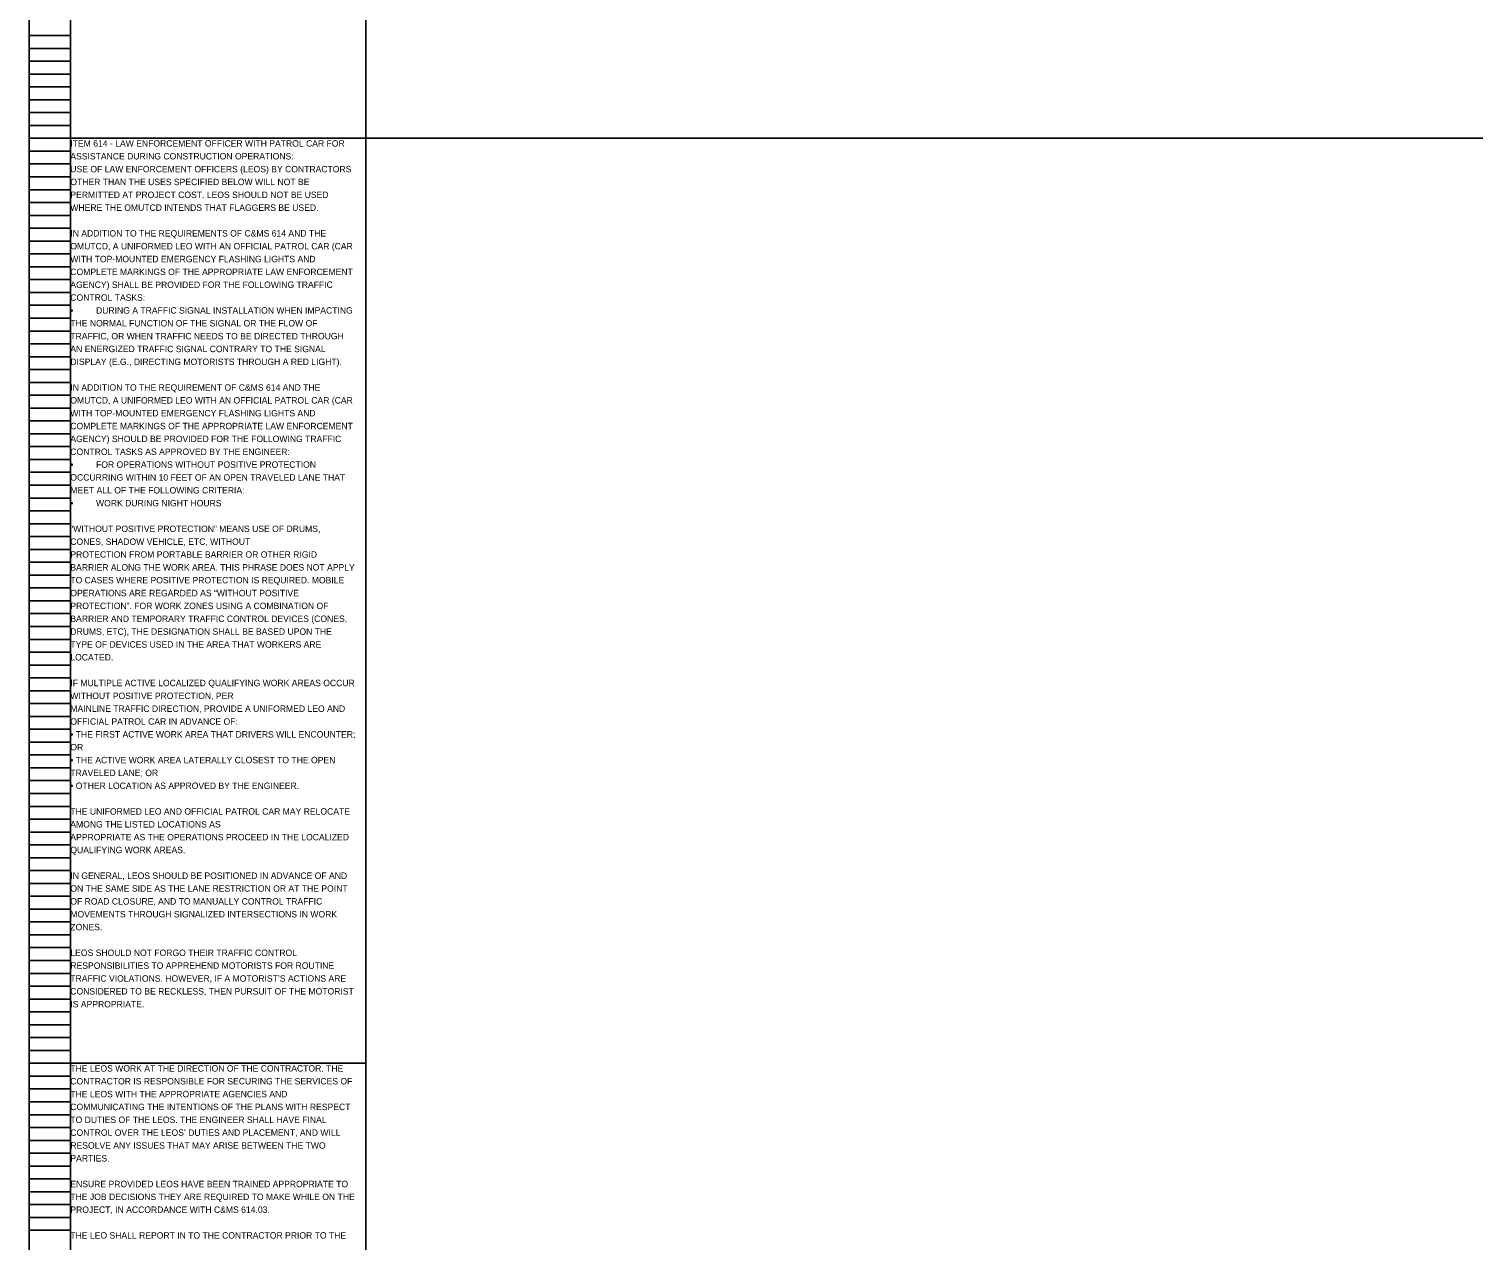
# Model space of a CAD drawing. Extents: x 16463 to 16500, y 5400 to 5823.
# Drawn here: x 16463.05 to 16494.74, y 5638.16 to 5664.57 of the extents above; entities that cross this region are included whole.
import ezdxf

# ---------------------------------------------------------------- set-up
doc = ezdxf.new("R2010")
doc.units = 0
for name, color, linetype in [('Default', 7, 'Continuous'), ('SC_Scratch1', 7, 'Continuous'), ('SH_Data', 7, 'Continuous')]:
    doc.layers.add(name, color=color, linetype=linetype)

msp = doc.modelspace()

# ---------------------------------------------------------------- linework, layer by layer
at = {"layer": 'SC_Scratch1'}
msp.add_line((16470.389, 5662.192), (16494.742, 5662.192), dxfattribs=at)
for points in [[(16463.949, 5682.352), (16470.389, 5682.352), (16470.389, 5662.192), (16463.949, 5662.192)], [(16463.949, 5662.192), (16470.389, 5662.192), (16470.389, 5642.032), (16463.949, 5642.032)], [(16463.949, 5642.032), (16470.389, 5642.032), (16470.389, 5621.872), (16463.949, 5621.872)]]:
    msp.add_lwpolyline(points, close=True, dxfattribs=at)
at = {"layer": 'SH_Data'}
for p, q in [((16463.049, 5662.192), (16463.049, 5682.352)), ((16463.949, 5662.192), (16463.949, 5682.352)), ((16463.049, 5664.432), (16463.949, 5664.432)), ((16463.049, 5664.152), (16463.949, 5664.152)), ((16463.049, 5663.872), (16463.949, 5663.872)), ((16463.049, 5663.592), (16463.949, 5663.592)), ((16463.049, 5663.312), (16463.949, 5663.312)), ((16463.049, 5663.032), (16463.949, 5663.032)), ((16463.049, 5662.752), (16463.949, 5662.752)), ((16463.049, 5662.472), (16463.949, 5662.472)), ((16463.049, 5642.032), (16463.049, 5662.192)), ((16463.049, 5662.192), (16463.949, 5662.192)), ((16463.049, 5662.192), (16463.949, 5662.192)), ((16463.949, 5642.032), (16463.949, 5662.192)), ((16463.049, 5661.912), (16463.949, 5661.912)), ((16463.049, 5661.632), (16463.949, 5661.632)), ((16463.049, 5661.352), (16463.949, 5661.352)), ((16463.049, 5661.072), (16463.949, 5661.072)), ((16463.049, 5660.792), (16463.949, 5660.792)), ((16463.049, 5660.512), (16463.949, 5660.512)), ((16463.049, 5660.232), (16463.949, 5660.232)), ((16463.049, 5659.952), (16463.949, 5659.952)), ((16463.049, 5659.672), (16463.949, 5659.672)), ((16463.049, 5659.392), (16463.949, 5659.392)), ((16463.049, 5659.112), (16463.949, 5659.112)), ((16463.049, 5658.832), (16463.949, 5658.832)), ((16463.049, 5658.552), (16463.949, 5658.552)), ((16463.049, 5658.272), (16463.949, 5658.272)), ((16463.049, 5657.992), (16463.949, 5657.992)), ((16463.049, 5657.712), (16463.949, 5657.712)), ((16463.049, 5657.432), (16463.949, 5657.432)), ((16463.049, 5657.152), (16463.949, 5657.152)), ((16463.049, 5656.872), (16463.949, 5656.872)), ((16463.049, 5656.592), (16463.949, 5656.592)), ((16463.049, 5656.312), (16463.949, 5656.312)), ((16463.049, 5656.032), (16463.949, 5656.032)), ((16463.049, 5655.752), (16463.949, 5655.752)), ((16463.049, 5655.472), (16463.949, 5655.472)), ((16463.049, 5655.192), (16463.949, 5655.192)), ((16463.049, 5654.912), (16463.949, 5654.912)), ((16463.049, 5654.632), (16463.949, 5654.632)), ((16463.049, 5654.352), (16463.949, 5654.352)), ((16463.049, 5654.072), (16463.949, 5654.072)), ((16463.049, 5653.792), (16463.949, 5653.792)), ((16463.049, 5653.512), (16463.949, 5653.512)), ((16463.049, 5653.232), (16463.949, 5653.232)), ((16463.049, 5652.952), (16463.949, 5652.952)), ((16463.049, 5652.672), (16463.949, 5652.672)), ((16463.049, 5652.392), (16463.949, 5652.392)), ((16463.049, 5652.112), (16463.949, 5652.112)), ((16463.049, 5651.832), (16463.949, 5651.832)), ((16463.049, 5651.552), (16463.949, 5651.552)), ((16463.049, 5651.272), (16463.949, 5651.272)), ((16463.049, 5650.992), (16463.949, 5650.992)), ((16463.049, 5650.712), (16463.949, 5650.712)), ((16463.049, 5650.432), (16463.949, 5650.432)), ((16463.049, 5650.152), (16463.949, 5650.152)), ((16463.049, 5649.872), (16463.949, 5649.872)), ((16463.049, 5649.592), (16463.949, 5649.592)), ((16463.049, 5649.312), (16463.949, 5649.312)), ((16463.049, 5649.032), (16463.949, 5649.032)), ((16463.049, 5648.752), (16463.949, 5648.752)), ((16463.049, 5648.472), (16463.949, 5648.472)), ((16463.049, 5648.192), (16463.949, 5648.192)), ((16463.049, 5647.912), (16463.949, 5647.912)), ((16463.049, 5647.632), (16463.949, 5647.632)), ((16463.049, 5647.352), (16463.949, 5647.352)), ((16463.049, 5647.072), (16463.949, 5647.072)), ((16463.049, 5646.792), (16463.949, 5646.792)), ((16463.049, 5646.512), (16463.949, 5646.512)), ((16463.049, 5646.232), (16463.949, 5646.232)), ((16463.049, 5645.952), (16463.949, 5645.952)), ((16463.049, 5645.672), (16463.949, 5645.672)), ((16463.049, 5645.392), (16463.949, 5645.392)), ((16463.049, 5645.112), (16463.949, 5645.112)), ((16463.049, 5644.832), (16463.949, 5644.832)), ((16463.049, 5644.552), (16463.949, 5644.552)), ((16463.049, 5644.272), (16463.949, 5644.272)), ((16463.049, 5643.992), (16463.949, 5643.992)), ((16463.049, 5643.712), (16463.949, 5643.712)), ((16463.049, 5643.432), (16463.949, 5643.432)), ((16463.049, 5643.152), (16463.949, 5643.152)), ((16463.049, 5642.872), (16463.949, 5642.872)), ((16463.049, 5642.592), (16463.949, 5642.592)), ((16463.049, 5642.312), (16463.949, 5642.312)), ((16463.049, 5621.872), (16463.049, 5642.032)), ((16463.049, 5642.032), (16463.949, 5642.032)), ((16463.049, 5642.032), (16463.949, 5642.032)), ((16463.949, 5621.872), (16463.949, 5642.032)), ((16463.049, 5641.752), (16463.949, 5641.752)), ((16463.049, 5641.472), (16463.949, 5641.472)), ((16463.049, 5641.192), (16463.949, 5641.192)), ((16463.049, 5640.912), (16463.949, 5640.912)), ((16463.049, 5640.632), (16463.949, 5640.632)), ((16463.049, 5640.352), (16463.949, 5640.352)), ((16463.049, 5640.072), (16463.949, 5640.072)), ((16463.049, 5639.792), (16463.949, 5639.792)), ((16463.049, 5639.512), (16463.949, 5639.512)), ((16463.049, 5639.232), (16463.949, 5639.232)), ((16463.049, 5638.952), (16463.949, 5638.952)), ((16463.049, 5638.672), (16463.949, 5638.672)), ((16463.049, 5638.392), (16463.949, 5638.392))]:
    msp.add_line(p, q, dxfattribs=at)

# ---------------------------------------------------------------- texts
at = {"layer": 'Default'}
for s, p in [('ASSISTANCE DURING CONSTRUCTION OPERATIONS:', (16463.949, 5661.731)), ('ITEM 614 - LAW ENFORCEMENT OFFICER WITH PATROL CAR FOR ', (16463.949, 5662.011)), ('USE OF LAW ENFORCEMENT OFFICERS (LEOS) BY CONTRACTORS ', (16463.949, 5661.451)), ('OTHER THAN THE USES SPECIFIED BELOW WILL NOT BE ', (16463.949, 5661.171)), ('PERMITTED AT PROJECT COST. LEOS SHOULD NOT BE USED ', (16463.949, 5660.891)), ('WHERE THE OMUTCD INTENDS THAT FLAGGERS BE USED.', (16463.949, 5660.611)), ('IN ADDITION TO THE REQUIREMENTS OF C&MS 614 AND THE ', (16463.949, 5660.051)), ('WITH TOP-MOUNTED EMERGENCY FLASHING LIGHTS AND ', (16463.949, 5659.491)), ('OMUTCD, A UNIFORMED LEO WITH AN OFFICIAL PATROL CAR (CAR ', (16463.949, 5659.771)), ('COMPLETE MARKINGS OF THE APPROPRIATE LAW ENFORCEMENT ', (16463.949, 5659.211)), ('AGENCY) SHALL BE PROVIDED FOR THE FOLLOWING TRAFFIC ', (16463.949, 5658.931)), ('CONTROL TASKS:', (16463.949, 5658.651)), ('•', (16463.949, 5658.371)), ('DURING A TRAFFIC SIGNAL INSTALLATION WHEN IMPACTING ', (16464.509, 5658.371)), ('THE NORMAL FUNCTION OF THE SIGNAL OR THE FLOW OF ', (16463.949, 5658.091)), ('TRAFFIC, OR WHEN TRAFFIC NEEDS TO BE DIRECTED THROUGH ', (16463.949, 5657.811)), ('AN ENERGIZED TRAFFIC SIGNAL CONTRARY TO THE SIGNAL ', (16463.949, 5657.531)), ('DISPLAY (E.G., DIRECTING MOTORISTS THROUGH A RED LIGHT). ', (16463.949, 5657.251)), ('IN ADDITION TO THE REQUIREMENT OF C&MS 614 AND THE ', (16463.949, 5656.691)), ('OMUTCD, A UNIFORMED LEO WITH AN OFFICIAL PATROL CAR (CAR ', (16463.949, 5656.411)), ('WITH TOP-MOUNTED EMERGENCY FLASHING LIGHTS AND ', (16463.949, 5656.131)), ('COMPLETE MARKINGS OF THE APPROPRIATE LAW ENFORCEMENT ', (16463.949, 5655.851)), ('AGENCY) SHOULD BE PROVIDED FOR THE FOLLOWING TRAFFIC ', (16463.949, 5655.571)), ('CONTROL TASKS AS APPROVED BY THE ENGINEER: ', (16463.949, 5655.291)), ('•', (16463.949, 5655.011)), ('OCCURRING WITHIN 10 FEET OF AN OPEN TRAVELED LANE THAT ', (16463.949, 5654.731)), ('FOR OPERATIONS WITHOUT POSITIVE PROTECTION ', (16464.509, 5655.011)), ('MEET ALL OF THE FOLLOWING CRITERIA:', (16463.949, 5654.451)), ('•', (16463.949, 5654.171)), ('WORK DURING NIGHT HOURS', (16464.509, 5654.171)), ('“WITHOUT POSITIVE PROTECTION” MEANS USE OF DRUMS, ', (16463.949, 5653.611)), ('CONES, SHADOW VEHICLE, ETC, WITHOUT', (16463.949, 5653.331)), ('PROTECTION FROM PORTABLE BARRIER OR OTHER RIGID ', (16463.949, 5653.051)), ('BARRIER ALONG THE WORK AREA. THIS PHRASE DOES NOT APPLY ', (16463.949, 5652.771)), ('TO CASES WHERE POSITIVE PROTECTION IS REQUIRED. MOBILE ', (16463.949, 5652.491)), ('OPERATIONS ARE REGARDED AS “WITHOUT POSITIVE ', (16463.949, 5652.211)), ('PROTECTION”. FOR WORK ZONES USING A COMBINATION OF ', (16463.949, 5651.931)), ('BARRIER AND TEMPORARY TRAFFIC CONTROL DEVICES (CONES, ', (16463.949, 5651.651)), ('DRUMS, ETC), THE DESIGNATION SHALL BE BASED UPON THE ', (16463.949, 5651.371)), ('TYPE OF DEVICES USED IN THE AREA THAT WORKERS ARE ', (16463.949, 5651.091)), ('LOCATED.', (16463.949, 5650.811)), ('WITHOUT POSITIVE PROTECTION, PER', (16463.949, 5649.971)), ('IF MULTIPLE ACTIVE LOCALIZED QUALIFYING WORK AREAS OCCUR ', (16463.949, 5650.251)), ('MAINLINE TRAFFIC DIRECTION, PROVIDE A UNIFORMED LEO AND ', (16463.949, 5649.691)), ('OFFICIAL PATROL CAR IN ADVANCE OF:', (16463.949, 5649.411)), ('• THE FIRST ACTIVE WORK AREA THAT DRIVERS WILL ENCOUNTER; ', (16463.949, 5649.131)), ('OR', (16463.949, 5648.851)), ('• THE ACTIVE WORK AREA LATERALLY CLOSEST TO THE OPEN ', (16463.949, 5648.571)), ('TRAVELED LANE; OR', (16463.949, 5648.291)), ('• OTHER LOCATION AS APPROVED BY THE ENGINEER.', (16463.949, 5648.011)), ('THE UNIFORMED LEO AND OFFICIAL PATROL CAR MAY RELOCATE ', (16463.949, 5647.451)), ('AMONG THE LISTED LOCATIONS AS', (16463.949, 5647.171)), ('APPROPRIATE AS THE OPERATIONS PROCEED IN THE LOCALIZED ', (16463.949, 5646.891)), ('QUALIFYING WORK AREAS.', (16463.949, 5646.611)), ('IN GENERAL, LEOS SHOULD BE POSITIONED IN ADVANCE OF AND ', (16463.949, 5646.051)), ('ON THE SAME SIDE AS THE LANE RESTRICTION OR AT THE POINT ', (16463.949, 5645.771)), ('OF ROAD CLOSURE, AND TO MANUALLY CONTROL TRAFFIC ', (16463.949, 5645.491)), ('ZONES. ', (16463.949, 5644.931)), ('MOVEMENTS THROUGH SIGNALIZED INTERSECTIONS IN WORK ', (16463.949, 5645.211)), ('LEOS SHOULD NOT FORGO THEIR TRAFFIC CONTROL ', (16463.949, 5644.371)), ('RESPONSIBILITIES TO APPREHEND MOTORISTS FOR ROUTINE ', (16463.949, 5644.091)), ('TRAFFIC VIOLATIONS. HOWEVER, IF A MOTORIST’S ACTIONS ARE ', (16463.949, 5643.811)), ('CONSIDERED TO BE RECKLESS, THEN PURSUIT OF THE MOTORIST ', (16463.949, 5643.531)), ('IS APPROPRIATE. ', (16463.949, 5643.251)), ('THE LEOS WORK AT THE DIRECTION OF THE CONTRACTOR. THE ', (16463.949, 5641.851)), ('CONTRACTOR IS RESPONSIBLE FOR SECURING THE SERVICES OF ', (16463.949, 5641.571)), ('THE LEOS WITH THE APPROPRIATE AGENCIES AND ', (16463.949, 5641.291)), ('COMMUNICATING THE INTENTIONS OF THE PLANS WITH RESPECT ', (16463.949, 5641.011)), ('TO DUTIES OF THE LEOS. THE ENGINEER SHALL HAVE FINAL ', (16463.949, 5640.731)), ('CONTROL OVER THE LEOS’ DUTIES AND PLACEMENT, AND WILL ', (16463.949, 5640.451)), ('RESOLVE ANY ISSUES THAT MAY ARISE BETWEEN THE TWO ', (16463.949, 5640.171)), ('PARTIES. ', (16463.949, 5639.891)), ('ENSURE PROVIDED LEOS HAVE BEEN TRAINED APPROPRIATE TO ', (16463.949, 5639.331)), ('THE JOB DECISIONS THEY ARE REQUIRED TO MAKE WHILE ON THE ', (16463.949, 5639.051)), ('PROJECT, IN ACCORDANCE WITH C&MS 614.03. ', (16463.949, 5638.771)), ('THE LEO SHALL REPORT IN TO THE CONTRACTOR PRIOR TO THE ', (16463.949, 5638.211))]:
    msp.add_text(s, height=0.14, dxfattribs=at).set_placement(p)

doc.saveas('drawing.dxf')
